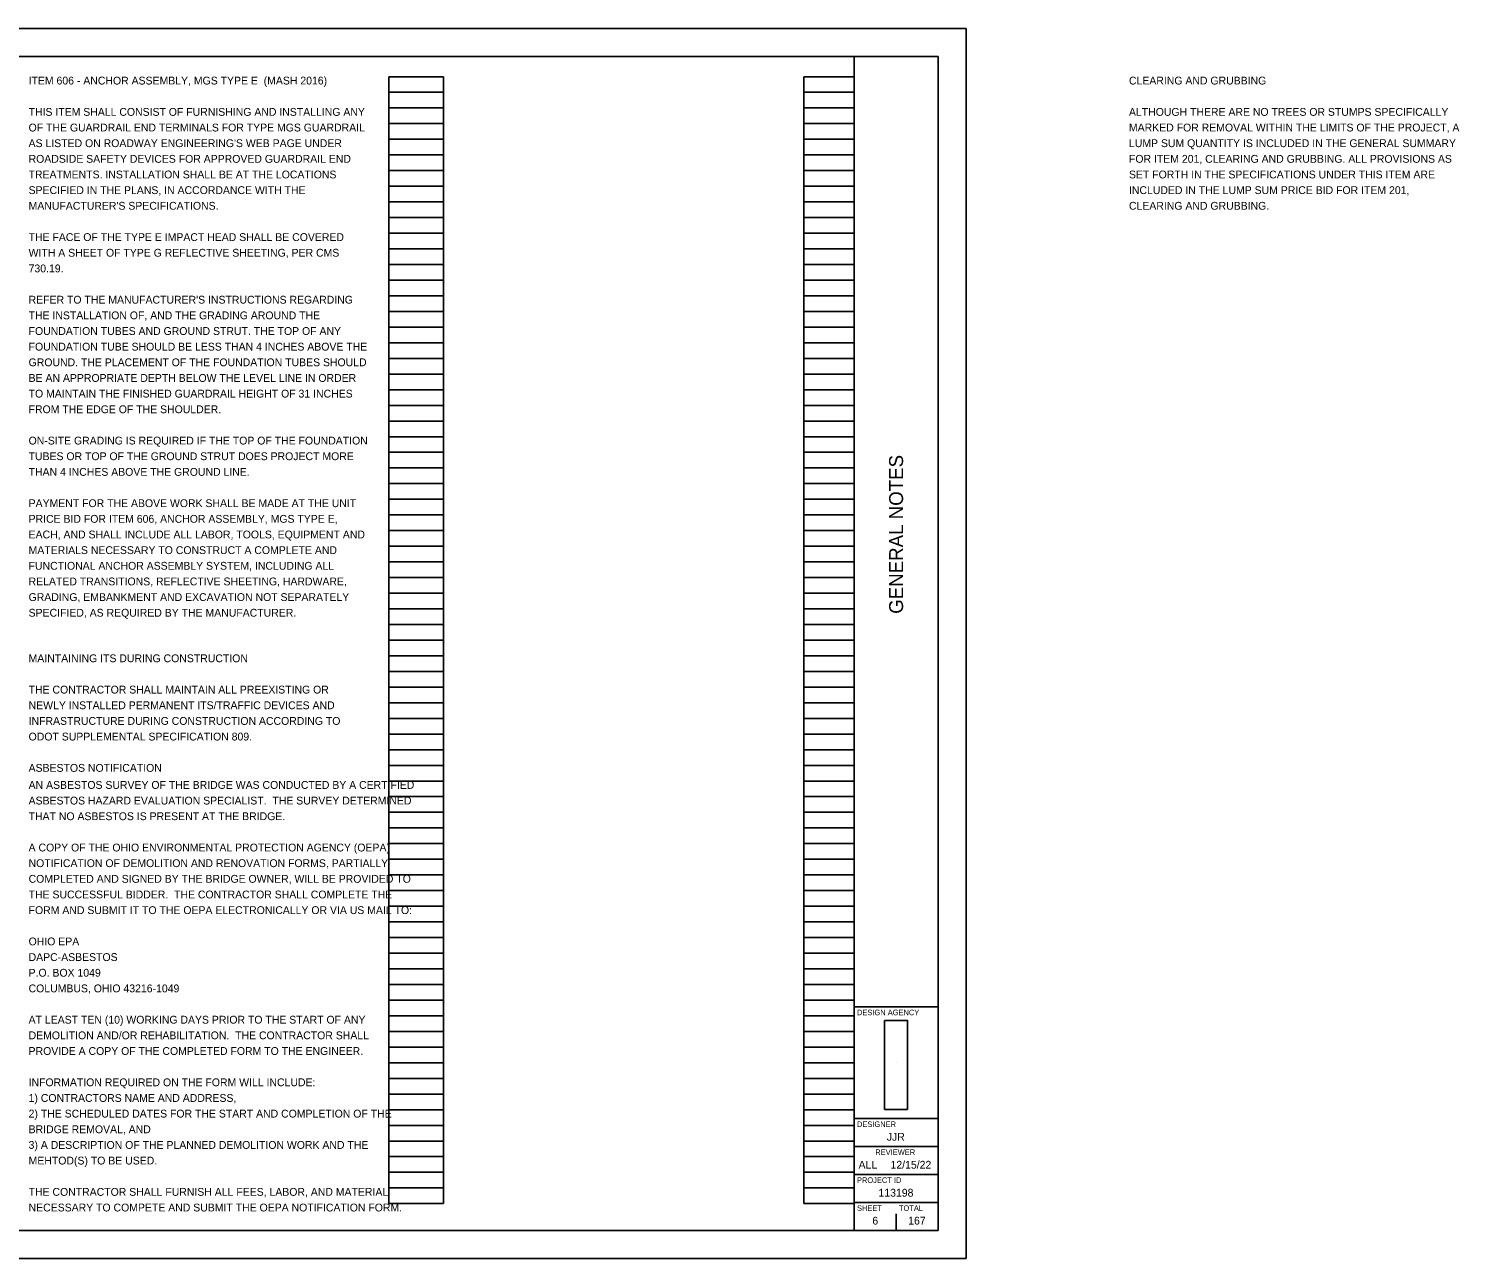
# Model space of a CAD drawing. Extents: x -5.5 to 42.8, y 0 to 22.
# Drawn here: x 17.24 to 42.82, y 0 to 22 of the extents above; entities that cross this region are included whole.
import ezdxf

# ---------------------------------------------------------------- set-up
doc = ezdxf.new("R2010")
doc.units = 0
for name, color, linetype in [('SH_Border', 7, 'Continuous'), ('SH_Cut_Line', 7, 'Continuous'), ('SH_Data', 7, 'Continuous'), ('SH_Text', 7, 'Continuous')]:
    doc.layers.add(name, color=color, linetype=linetype)

msp = doc.modelspace()

# ---------------------------------------------------------------- linework, layer by layer
at = {"layer": 'SH_Border'}
for p, q in [((32, 0.5), (32, 21.5)), ((32, 4.5), (33.5, 4.5)), ((32, 2.5), (33.5, 2.5)), ((32, 2), (33.5, 2)), ((32, 1.5), (33.5, 1.5)), ((32, 1), (33.5, 1))]:
    msp.add_line(p, q, dxfattribs=at)
msp.add_lwpolyline([(1.5, 21.5), (33.5, 21.5), (33.5, 0.5), (1.5, 0.5)], close=True, dxfattribs=at)
at = {"layer": 'SH_Cut_Line'}
msp.add_lwpolyline([(0, 0), (34, 0), (34, 22), (0, 22)], close=True, dxfattribs=at)
at = {"layer": 'SH_Data'}
for p, q in [((23.68, 0.98), (23.68, 21.14)), ((23.68, 21.14), (24.66, 21.14)), ((24.66, 0.98), (24.66, 21.14)), ((31.1, 0.98), (31.1, 21.14)), ((31.1, 21.14), (32, 21.14)), ((32, 0.98), (32, 21.14)), ((23.68, 20.86), (24.66, 20.86)), ((31.1, 20.86), (32, 20.86)), ((23.68, 20.58), (24.66, 20.58)), ((31.1, 20.58), (32, 20.58)), ((23.68, 20.3), (24.66, 20.3)), ((31.1, 20.3), (32, 20.3)), ((23.68, 20.02), (24.66, 20.02)), ((31.1, 20.02), (32, 20.02)), ((23.68, 19.74), (24.66, 19.74)), ((31.1, 19.74), (32, 19.74)), ((23.68, 19.46), (24.66, 19.46)), ((31.1, 19.46), (32, 19.46)), ((23.68, 19.18), (24.66, 19.18)), ((31.1, 19.18), (32, 19.18)), ((23.68, 18.9), (24.66, 18.9)), ((31.1, 18.9), (32, 18.9)), ((23.68, 18.62), (24.66, 18.62)), ((31.1, 18.62), (32, 18.62)), ((23.68, 18.34), (24.66, 18.34)), ((31.1, 18.34), (32, 18.34)), ((23.68, 18.06), (24.66, 18.06)), ((31.1, 18.06), (32, 18.06)), ((23.68, 17.78), (24.66, 17.78)), ((31.1, 17.78), (32, 17.78)), ((23.68, 17.5), (24.66, 17.5)), ((31.1, 17.5), (32, 17.5)), ((23.68, 17.22), (24.66, 17.22)), ((31.1, 17.22), (32, 17.22)), ((23.68, 16.94), (24.66, 16.94)), ((31.1, 16.94), (32, 16.94)), ((23.68, 16.66), (24.66, 16.66)), ((31.1, 16.66), (32, 16.66)), ((23.68, 16.38), (24.66, 16.38)), ((31.1, 16.38), (32, 16.38)), ((23.68, 16.1), (24.66, 16.1)), ((31.1, 16.1), (32, 16.1)), ((23.68, 15.82), (24.66, 15.82)), ((31.1, 15.82), (32, 15.82)), ((23.68, 15.54), (24.66, 15.54)), ((31.1, 15.54), (32, 15.54)), ((23.68, 15.26), (24.66, 15.26)), ((31.1, 15.26), (32, 15.26)), ((23.68, 14.98), (24.66, 14.98)), ((31.1, 14.98), (32, 14.98)), ((23.68, 14.7), (24.66, 14.7)), ((31.1, 14.7), (32, 14.7)), ((23.68, 14.42), (24.66, 14.42)), ((31.1, 14.42), (32, 14.42)), ((23.68, 14.14), (24.66, 14.14)), ((31.1, 14.14), (32, 14.14)), ((23.68, 13.86), (24.66, 13.86)), ((31.1, 13.86), (32, 13.86)), ((23.68, 13.58), (24.66, 13.58)), ((31.1, 13.58), (32, 13.58)), ((23.68, 13.3), (24.66, 13.3)), ((31.1, 13.3), (32, 13.3)), ((23.68, 13.02), (24.66, 13.02)), ((31.1, 13.02), (32, 13.02)), ((23.68, 12.74), (24.66, 12.74)), ((31.1, 12.74), (32, 12.74)), ((23.68, 12.46), (24.66, 12.46)), ((31.1, 12.46), (32, 12.46)), ((23.68, 12.18), (24.66, 12.18)), ((31.1, 12.18), (32, 12.18)), ((23.68, 11.9), (24.66, 11.9)), ((31.1, 11.9), (32, 11.9)), ((23.68, 11.62), (24.66, 11.62)), ((31.1, 11.62), (32, 11.62)), ((23.68, 11.34), (24.66, 11.34)), ((31.1, 11.34), (32, 11.34)), ((23.68, 11.06), (24.66, 11.06)), ((31.1, 11.06), (32, 11.06)), ((23.68, 10.78), (24.66, 10.78)), ((31.1, 10.78), (32, 10.78)), ((23.68, 10.5), (24.66, 10.5)), ((31.1, 10.5), (32, 10.5)), ((23.68, 10.22), (24.66, 10.22)), ((31.1, 10.22), (32, 10.22)), ((23.68, 9.94), (24.66, 9.94)), ((31.1, 9.94), (32, 9.94)), ((23.68, 9.66), (24.66, 9.66)), ((31.1, 9.66), (32, 9.66)), ((23.68, 9.38), (24.66, 9.38)), ((31.1, 9.38), (32, 9.38)), ((23.68, 9.1), (24.66, 9.1)), ((31.1, 9.1), (32, 9.1)), ((23.68, 8.82), (24.66, 8.82)), ((31.1, 8.82), (32, 8.82)), ((23.68, 8.54), (24.66, 8.54)), ((31.1, 8.54), (32, 8.54)), ((23.68, 8.26), (24.66, 8.26)), ((31.1, 8.26), (32, 8.26)), ((23.68, 7.98), (24.66, 7.98)), ((31.1, 7.98), (32, 7.98)), ((23.68, 7.7), (24.66, 7.7)), ((31.1, 7.7), (32, 7.7)), ((23.68, 7.42), (24.66, 7.42)), ((31.1, 7.42), (32, 7.42)), ((23.68, 7.14), (24.66, 7.14)), ((31.1, 7.14), (32, 7.14)), ((23.68, 6.86), (24.66, 6.86)), ((31.1, 6.86), (32, 6.86)), ((23.68, 6.58), (24.66, 6.58)), ((31.1, 6.58), (32, 6.58)), ((23.68, 6.3), (24.66, 6.3)), ((31.1, 6.3), (32, 6.3)), ((23.68, 6.02), (24.66, 6.02)), ((31.1, 6.02), (32, 6.02)), ((23.68, 5.74), (24.66, 5.74)), ((31.1, 5.74), (32, 5.74)), ((23.68, 5.46), (24.66, 5.46)), ((31.1, 5.46), (32, 5.46)), ((23.68, 5.18), (24.66, 5.18)), ((31.1, 5.18), (32, 5.18)), ((23.68, 4.9), (24.66, 4.9)), ((31.1, 4.9), (32, 4.9)), ((23.68, 4.62), (24.66, 4.62)), ((31.1, 4.62), (32, 4.62)), ((23.68, 4.34), (24.66, 4.34)), ((31.1, 4.34), (32, 4.34)), ((23.68, 4.06), (24.66, 4.06)), ((31.1, 4.06), (32, 4.06)), ((23.68, 3.78), (24.66, 3.78)), ((31.1, 3.78), (32, 3.78)), ((23.68, 3.5), (24.66, 3.5)), ((31.1, 3.5), (32, 3.5)), ((32.75, 3.5), (32.75, 3.5)), ((23.68, 3.22), (24.66, 3.22)), ((31.1, 3.22), (32, 3.22)), ((23.68, 2.94), (24.66, 2.94)), ((31.1, 2.94), (32, 2.94)), ((23.68, 2.66), (24.66, 2.66)), ((31.1, 2.66), (32, 2.66)), ((23.68, 2.38), (24.66, 2.38)), ((31.1, 2.38), (32, 2.38)), ((23.68, 2.1), (24.66, 2.1)), ((31.1, 2.1), (32, 2.1)), ((23.68, 1.82), (24.66, 1.82)), ((31.1, 1.82), (32, 1.82)), ((23.68, 1.54), (24.66, 1.54)), ((31.1, 1.54), (32, 1.54)), ((23.68, 1.26), (24.66, 1.26)), ((31.1, 1.26), (32, 1.26)), ((23.68, 0.98), (24.66, 0.98)), ((31.1, 0.98), (32, 0.98)), ((32.75, 0.5), (32.75, 0.8)), ((32.375, 0.675), (32.375, 0.675))]:
    msp.add_line(p, q, dxfattribs=at)
at = {"layer": 'SH_Text'}
msp.add_lwpolyline([(32.956, 2.664), (32.956, 4.254), (32.544, 4.254), (32.544, 2.664)], close=True, dxfattribs=at)

# ---------------------------------------------------------------- texts
at = {"layer": 'SH_Data'}
msp.add_text('GENERAL NOTES', height=0.25, rotation=90, dxfattribs=at).set_placement((32.875, 11.531))
for s, height, p in [('DESIGN AGENCY', 0.1, (32.05, 4.35)), ('DESIGNER', 0.1, (32.05, 2.35)), ('JJR', 0.14, (32.583, 2.105)), ('REVIEWER', 0.1, (32.378, 1.85)), ('ALL', 0.14, (32.079, 1.605)), ('12/15/22', 0.14, (32.65, 1.605)), ('PROJECT ID', 0.1, (32.05, 1.35)), ('113198', 0.14, (32.435, 1.105)), ('SHEET', 0.1, (32.05, 0.85)), ('TOTAL', 0.1, (32.8, 0.85)), ('6', 0.14, (32.325, 0.605)), ('167', 0.14, (32.966, 0.605))]:
    msp.add_text(s, height=height, dxfattribs=at).set_placement(p)
at = {"layer": 'SH_Text'}
for s, p in [('ITEM 606 - ANCHOR ASSEMBLY, MGS TYPE E  (MASH 2016)', (17.24, 21)), ('CLEARING AND GRUBBING', (36.913, 21)), ('THIS ITEM SHALL CONSIST OF FURNISHING AND INSTALLING ANY', (17.24, 20.44)), ('ALTHOUGH THERE ARE NO TREES OR STUMPS SPECIFICALLY', (36.913, 20.44)), ('OF THE GUARDRAIL END TERMINALS FOR TYPE MGS GUARDRAIL', (17.24, 20.16)), ('MARKED FOR REMOVAL WITHIN THE LIMITS OF THE PROJECT, A', (36.913, 20.16)), ("AS LISTED ON ROADWAY ENGINEERING'S WEB PAGE UNDER", (17.24, 19.88)), ('LUMP SUM QUANTITY IS INCLUDED IN THE GENERAL SUMMARY', (36.913, 19.88)), ('ROADSIDE SAFETY DEVICES FOR APPROVED GUARDRAIL END', (17.24, 19.6)), ('FOR ITEM 201, CLEARING AND GRUBBING. ALL PROVISIONS AS', (36.913, 19.6)), ('TREATMENTS. INSTALLATION SHALL BE AT THE LOCATIONS', (17.24, 19.32)), ('SET FORTH IN THE SPECIFICATIONS UNDER THIS ITEM ARE', (36.913, 19.32)), ('SPECIFIED IN THE PLANS, IN ACCORDANCE WITH THE', (17.24, 19.04)), ('INCLUDED IN THE LUMP SUM PRICE BID FOR ITEM 201,', (36.913, 19.04)), ("MANUFACTURER'S SPECIFICATIONS.", (17.24, 18.76)), ('CLEARING AND GRUBBING.', (36.913, 18.76)), ('THE FACE OF THE TYPE E IMPACT HEAD SHALL BE COVERED', (17.24, 18.2)), ('WITH A SHEET OF TYPE G REFLECTIVE SHEETING, PER CMS', (17.24, 17.92)), ('730.19.', (17.24, 17.64)), ("REFER TO THE MANUFACTURER'S INSTRUCTIONS REGARDING", (17.24, 17.08)), ('THE INSTALLATION OF, AND THE GRADING AROUND THE', (17.24, 16.8)), ('FOUNDATION TUBES AND GROUND STRUT. THE TOP OF ANY', (17.24, 16.52)), ('FOUNDATION TUBE SHOULD BE LESS THAN 4 INCHES ABOVE THE', (17.24, 16.24)), ('GROUND. THE PLACEMENT OF THE FOUNDATION TUBES SHOULD', (17.24, 15.96)), ('BE AN APPROPRIATE DEPTH BELOW THE LEVEL LINE IN ORDER', (17.24, 15.68)), ('TO MAINTAIN THE FINISHED GUARDRAIL HEIGHT OF 31 INCHES', (17.24, 15.4)), ('FROM THE EDGE OF THE SHOULDER.', (17.24, 15.12)), ('ON-SITE GRADING IS REQUIRED IF THE TOP OF THE FOUNDATION', (17.24, 14.56)), ('TUBES OR TOP OF THE GROUND STRUT DOES PROJECT MORE', (17.24, 14.28)), ('THAN 4 INCHES ABOVE THE GROUND LINE.', (17.24, 14)), ('PAYMENT FOR THE ABOVE WORK SHALL BE MADE AT THE UNIT', (17.24, 13.44)), ('PRICE BID FOR ITEM 606, ANCHOR ASSEMBLY, MGS TYPE E,', (17.24, 13.16)), ('EACH, AND SHALL INCLUDE ALL LABOR, TOOLS, EQUIPMENT AND', (17.24, 12.88)), ('MATERIALS NECESSARY TO CONSTRUCT A COMPLETE AND', (17.24, 12.6)), ('FUNCTIONAL ANCHOR ASSEMBLY SYSTEM, INCLUDING ALL', (17.24, 12.32)), ('RELATED TRANSITIONS, REFLECTIVE SHEETING, HARDWARE,', (17.24, 12.04)), ('GRADING, EMBANKMENT AND EXCAVATION NOT SEPARATELY', (17.24, 11.76)), ('SPECIFIED, AS REQUIRED BY THE MANUFACTURER.', (17.24, 11.48)), ('MAINTAINING ITS DURING CONSTRUCTION', (17.24, 10.665)), ('THE CONTRACTOR SHALL MAINTAIN ALL PREEXISTING OR', (17.24, 10.105)), ('NEWLY INSTALLED PERMANENT ITS/TRAFFIC DEVICES AND', (17.24, 9.825)), ('INFRASTRUCTURE DURING CONSTRUCTION ACCORDING TO', (17.24, 9.545)), ('ODOT SUPPLEMENTAL SPECIFICATION 809.', (17.24, 9.265)), ('ASBESTOS NOTIFICATION', (17.24, 8.705)), ('AN ASBESTOS SURVEY OF THE BRIDGE WAS CONDUCTED BY A CERTIFIED ', (17.24, 8.4)), ('ASBESTOS HAZARD EVALUATION SPECIALIST.  THE SURVEY DETERMINED ', (17.24, 8.12)), ('THAT NO ASBESTOS IS PRESENT AT THE BRIDGE.', (17.24, 7.84)), ('A COPY OF THE OHIO ENVIRONMENTAL PROTECTION AGENCY (OEPA) ', (17.24, 7.28)), ('NOTIFICATION OF DEMOLITION AND RENOVATION FORMS, PARTIALLY ', (17.24, 7)), ('COMPLETED AND SIGNED BY THE BRIDGE OWNER, WILL BE PROVIDED TO ', (17.24, 6.72)), ('THE SUCCESSFUL BIDDER.  THE CONTRACTOR SHALL COMPLETE THE ', (17.24, 6.44)), ('FORM AND SUBMIT IT TO THE OEPA ELECTRONICALLY OR VIA US MAIL TO:', (17.24, 6.16)), ('OHIO EPA', (17.24, 5.6)), ('DAPC-ASBESTOS', (17.24, 5.32)), ('P.O. BOX 1049', (17.24, 5.04)), ('COLUMBUS, OHIO 43216-1049', (17.24, 4.76)), ('AT LEAST TEN (10) WORKING DAYS PRIOR TO THE START OF ANY ', (17.24, 4.2)), ('DEMOLITION AND/OR REHABILITATION.  THE CONTRACTOR SHALL ', (17.24, 3.92)), ('PROVIDE A COPY OF THE COMPLETED FORM TO THE ENGINEER.', (17.24, 3.64)), ('INFORMATION REQUIRED ON THE FORM WILL INCLUDE:', (17.24, 3.08)), ('1) CONTRACTORS NAME AND ADDRESS,', (17.24, 2.8)), ('2) THE SCHEDULED DATES FOR THE START AND COMPLETION OF THE ', (17.24, 2.52)), ('BRIDGE REMOVAL, AND', (17.24, 2.24)), ('3) A DESCRIPTION OF THE PLANNED DEMOLITION WORK AND THE ', (17.24, 1.96)), ('MEHTOD(S) TO BE USED.', (17.24, 1.68)), ('THE CONTRACTOR SHALL FURNISH ALL FEES, LABOR, AND MATERIAL ', (17.24, 1.12)), ('NECESSARY TO COMPETE AND SUBMIT THE OEPA NOTIFICATION FORM.', (17.24, 0.84))]:
    msp.add_text(s, height=0.14, dxfattribs=at).set_placement(p)

doc.saveas('drawing.dxf')
